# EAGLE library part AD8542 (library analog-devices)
General-Purpose CMOS Rail-to-Rail Amplifiers Source: http://www.analog.com/static/imported-files/data_sheets/AD8541_8542_8544.pdf
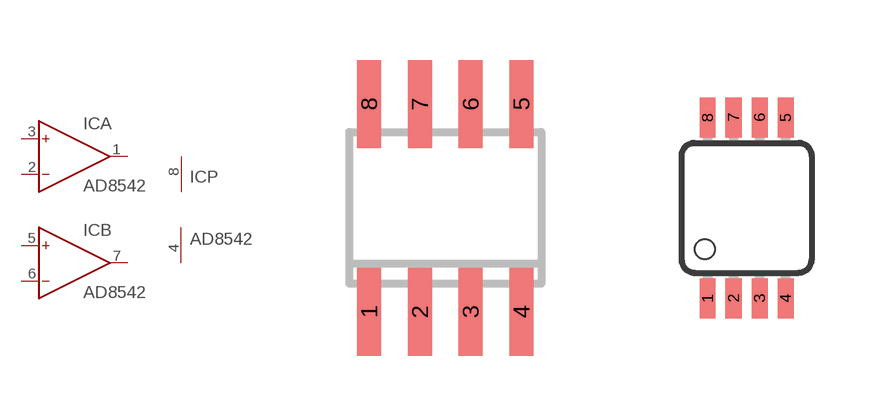
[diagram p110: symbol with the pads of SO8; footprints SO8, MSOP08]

Designator prefix IC; gates A=OP B=OP P=PWR+-

## AD8542R (MF: ALTERA CORPORATION; MPN: AD8542ARZ-REEL; OC_FARNELL: 1424150; OC_NEWARK: 59K6827)  [SO8]
1  A:OUT  out
2  A:IN-  in
3  A:IN+  in
4  P:V-  pwr
5  B:IN+  in
6  B:IN-  in
7  B:OUT  out
8  P:V+  pwr

## AD8542RM (MPN: AD8542ARZ; OC_FARNELL: 1464965; OC_NEWARK: 19M0965)  [MSOP08]
Pads as for SO8

## AD8542RU (MF: ALTERA CORPORATION; MPN: AD8542ARUZ; OC_FARNELL: 1333256; OC_NEWARK: 88H0269)  [TSSOP8]
Pads as for SO8

## Footprint SO8 (pad centres in mm)
8-Lead Small Outline IC (SO-8) Source: http://www.analog.com/UploadedFiles/Data_Sheets/703465986AD8611_2_0.pdf
smd 0.6 x 2.2: 1 -1.905,-2.6; 2 -0.635,-2.6; 3 0.635,-2.6; 4 1.905,-2.6; 5 1.905,2.6; 6 0.635,2.6; 7 -0.635,2.6; 8 -1.905,2.6

## Footprint MSOP08 (pad centres in mm)
8-Lead micro SO (RM-8) Source: http://www.analog.com/UploadedFiles/Data_Sheets/703465986AD8611_2_0.pdf
smd 0.4 x 1: 1 -0.976,-2.263; 2 -0.326,-2.263; 3 0.324,-2.263; 4 0.974,-2.263; 5 0.974,2.262; 6 0.324,2.262; 7 -0.326,2.262; 8 -0.976,2.262

## Footprint TSSOP8 (pad centres in mm)
8-Lead Thin Shrink Small Outline Package Source: http://www.analog.com/static/imported-files/data_sheets/AD8541_8542_8544.pdf
smd 0.9 x 0.35: 1 -2.875,0.975; 2 -2.875,0.325; 3 -2.875,-0.325; 4 -2.875,-0.975; 5 2.875,-0.975; 6 2.875,-0.325; 7 2.875,0.325; 8 2.875,0.975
